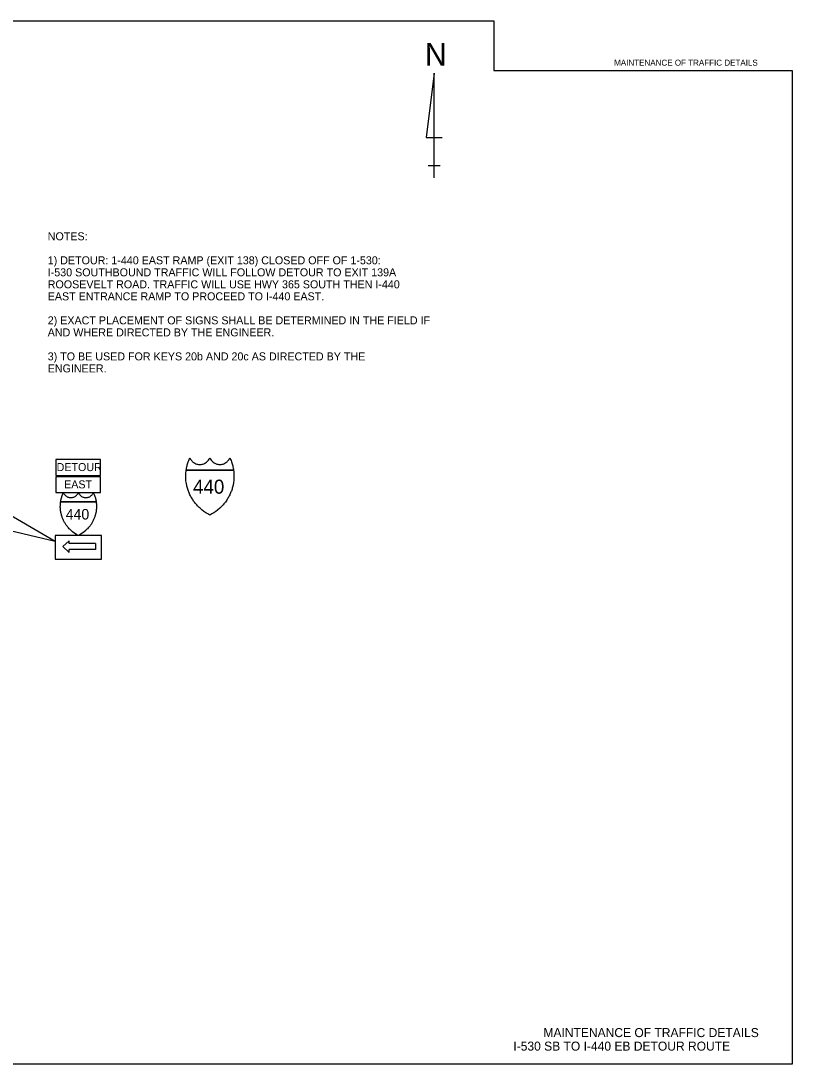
# Model space of a CAD drawing. Extents: x 754662 to 914198, y 935180 to 1039412.
# Drawn here: x 837096 to 914198, y 935180 to 1039412 of the extents above; entities that cross this region are included whole.
import ezdxf

# ---------------------------------------------------------------- set-up
doc = ezdxf.new("R2010")
doc.units = 0
for name, color, linetype in [('G-ANNO-TEXT', 7, 'Continuous'), ('G-No Plot-Anchor', 7, 'Continuous'), ('Level 14', 7, 'Continuous'), ('Level 61', 7, 'Continuous'), ('Level 62', 7, 'Continuous'), ('R_Draft', 7, 'Continuous')]:
    doc.layers.add(name, color=color, linetype=linetype)

msp = doc.modelspace()

# ---------------------------------------------------------------- linework, layer by layer
at = {"layer": 'G-No Plot-Anchor'}
msp.add_lwpolyline([(870863, 1039412), (884363, 1039412), (884363, 1034457), (914198, 1034457), (914198, 935180), (754662, 935180), (754662, 1039412)], close=True, dxfattribs=at)
at = {"layer": 'Level 14'}
for points in [[(853626, 994520), (853643, 994633), (853661, 994733), (853687, 994862), (853707, 994946), (853732, 995045), (853765, 995163), (853795, 995261), (853829, 995362), (853874, 995486), (853921, 995602), (853959, 995693), (853991, 995764), (854026, 995687), (854066, 995614), (854111, 995547), (854168, 995472), (854214, 995422), (854270, 995367), (854327, 995320), (854389, 995275), (854487, 995216), (854587, 995169), (854679, 995137), (854769, 995114), (854865, 995098), (854978, 995090), (855051, 995092), (855136, 995100), (855212, 995113), (855292, 995132), (855374, 995159), (855483, 995208), (855559, 995250), (855646, 995310), (855731, 995381), (855792, 995443), (855862, 995528), (855920, 995614), (855954, 995675), (855991, 995755)], [(855991, 995755), (856028, 995675), (856062, 995614), (856120, 995528), (856190, 995443), (856252, 995381), (856336, 995310), (856423, 995250), (856499, 995208), (856608, 995159), (856690, 995132), (856771, 995113), (856846, 995100), (856931, 995092), (857005, 995090), (857117, 995098), (857214, 995114), (857304, 995137), (857395, 995169), (857495, 995216), (857594, 995275), (857655, 995320), (857712, 995367), (857769, 995422), (857814, 995472), (857872, 995547), (857916, 995614), (857956, 995687), (857991, 995764), (858023, 995693), (858062, 995602), (858108, 995486), (858153, 995362), (858187, 995261), (858217, 995163), (858250, 995045), (858275, 994946), (858295, 994862), (858321, 994733), (858339, 994633), (858357, 994520)], [(855991, 990038), (855784, 990149), (855601, 990259), (855401, 990394), (855214, 990536), (855009, 990710), (854932, 990781), (854846, 990867), (854765, 990950), (854677, 991046), (854590, 991147), (854518, 991236), (854440, 991338), (854369, 991436), (854307, 991527), (854253, 991610), (854208, 991682), (854149, 991783), (854103, 991866), (854052, 991963), (854003, 992063), (853960, 992155), (853921, 992245), (853881, 992345), (853845, 992438), (853811, 992535), (853778, 992636), (853747, 992739), (853720, 992838), (853696, 992932), (853677, 993016), (853664, 993078), (853642, 993199), (853620, 993338), (853605, 993454), (853595, 993576), (853588, 993675), (853584, 993800), (853583, 993917), (853585, 994047), (853589, 994133), (853593, 994211), (853597, 994261), (853609, 994389), (853626, 994520)], [(858357, 994520), (853626, 994520)], [(853626, 994520), (858357, 994520)], [(858357, 994520), (858373, 994389), (858385, 994261), (858389, 994211), (858394, 994133), (858397, 994047), (858400, 993917), (858398, 993800), (858394, 993675), (858388, 993576), (858377, 993454), (858362, 993338), (858341, 993199), (858318, 993078), (858305, 993016), (858286, 992932), (858263, 992838), (858235, 992739), (858204, 992636), (858171, 992535), (858137, 992438), (858102, 992345), (858061, 992245), (858022, 992155), (857979, 992063), (857930, 991963), (857879, 991866), (857833, 991783), (857774, 991682), (857729, 991610), (857675, 991527), (857613, 991436), (857542, 991338), (857464, 991236), (857392, 991147), (857305, 991046), (857217, 990950), (857137, 990867), (857050, 990781), (856973, 990710), (856769, 990536), (856581, 990394), (856381, 990259), (856198, 990149), (855991, 990038)], [(842848, 987991), (842692, 988074), (842556, 988156), (842405, 988258), (842265, 988364), (842111, 988495), (842054, 988549), (841989, 988612), (841928, 988675), (841862, 988747), (841797, 988823), (841743, 988889), (841684, 988966), (841631, 989040), (841585, 989107), (841544, 989170), (841511, 989224), (841466, 989300), (841432, 989362), (841394, 989434), (841357, 989509), (841325, 989579), (841296, 989646), (841265, 989721), (841238, 989791), (841213, 989863), (841188, 989939), (841165, 990017), (841144, 990091), (841127, 990162), (841112, 990225), (841103, 990271), (841086, 990362), (841069, 990466), (841058, 990553), (841050, 990644), (841046, 990719), (841042, 990813), (841041, 990900), (841043, 990998), (841046, 991062), (841049, 991121), (841052, 991158), (841061, 991254), (841074, 991352)], [(841074, 991352), (841087, 991437), (841100, 991512), (841120, 991609), (841134, 991672), (841153, 991747), (841178, 991835), (841201, 991908), (841226, 991984), (841260, 992077), (841295, 992164), (841324, 992232), (841348, 992285), (841374, 992228), (841404, 992173), (841437, 992122), (841481, 992067), (841515, 992029), (841557, 991988), (841600, 991952), (841646, 991919), (841719, 991874), (841795, 991839), (841863, 991815), (841931, 991798), (842003, 991786), (842088, 991780), (842143, 991781), (842207, 991787), (842263, 991797), (842324, 991812), (842385, 991832), (842467, 991868), (842523, 991900), (842589, 991945), (842652, 991998), (842698, 992044), (842751, 992108), (842794, 992173), (842820, 992219), (842848, 992279)], [(844622, 991352), (841074, 991352)], [(841074, 991352), (844622, 991352)], [(842848, 992279), (842876, 992219), (842901, 992173), (842945, 992108), (842997, 992044), (843043, 991998), (843106, 991945), (843172, 991900), (843229, 991868), (843311, 991832), (843372, 991812), (843432, 991797), (843489, 991787), (843553, 991781), (843608, 991780), (843692, 991786), (843765, 991798), (843832, 991815), (843900, 991839), (843976, 991874), (844050, 991919), (844096, 991952), (844139, 991988), (844181, 992029), (844215, 992067), (844258, 992122), (844291, 992173), (844321, 992228), (844348, 992285), (844372, 992232), (844401, 992164), (844435, 992077), (844469, 991984), (844495, 991908), (844517, 991835), (844542, 991747), (844561, 991672), (844576, 991609), (844596, 991512), (844609, 991437), (844622, 991352)], [(844622, 991352), (844634, 991254), (844643, 991158), (844646, 991121), (844650, 991062), (844652, 990998), (844654, 990900), (844653, 990813), (844650, 990719), (844645, 990644), (844637, 990553), (844626, 990466), (844610, 990362), (844593, 990271), (844583, 990225), (844569, 990162), (844551, 990091), (844531, 990017), (844508, 989939), (844483, 989863), (844457, 989791), (844431, 989721), (844400, 989646), (844371, 989579), (844339, 989509), (844302, 989434), (844264, 989362), (844229, 989300), (844185, 989224), (844151, 989170), (844111, 989107), (844065, 989040), (844011, 988966), (843953, 988889), (843898, 988823), (843833, 988747), (843767, 988675), (843707, 988612), (843642, 988549), (843584, 988495), (843431, 988364), (843290, 988258), (843140, 988156), (843003, 988074), (842848, 987991)]]:
    msp.add_lwpolyline(points, dxfattribs=at)
at = {"layer": 'Level 61'}
msp.add_line((844567, 987181), (844567, 986595), dxfattribs=at)
at = {"layer": 'Level 62'}
for p, q in [((841292, 986888), (841935, 987474)), ((841935, 987181), (841935, 987474)), ((844567, 987181), (841935, 987181)), ((841935, 986302), (841292, 986888)), ((844567, 986595), (841935, 986595)), ((841935, 986302), (841935, 986595))]:
    msp.add_line(p, q, dxfattribs=at)
for points in [[(840604, 994006), (845060, 994006), (845060, 995579), (840604, 995579)], [(840604, 992279), (845060, 992279), (845060, 993852), (840604, 993852)], [(840540, 985630), (845156, 985630), (845156, 987991), (840540, 987991)]]:
    msp.add_lwpolyline(points, close=True, dxfattribs=at)
at = {"layer": 'R_Draft'}
for p, q in [((878417, 1034171), (877615, 1027755)), ((878417, 1023745), (878417, 1034171)), ((877615, 1027755), (879219, 1027755)), ((877811, 1024963), (879014, 1024963)), ((840540, 987412), (813952, 1002723)), ((840540, 987412), (828507, 990224))]:
    msp.add_line(p, q, dxfattribs=at)

# ---------------------------------------------------------------- texts
at = {"layer": 'G-ANNO-TEXT'}
for s, height, p in [('MAINTENANCE OF TRAFFIC DETAILS', 600, (896406, 1034935)), ('440', 1402.1, (854306, 992171)), ('440', 1051.6, (841584, 989591)), ('MAINTENANCE OF TRAFFIC DETAILS', 900, (889335, 937880)), ('I-530 SB TO I-440 EB DETOUR ROUTE', 900, (886330, 936530))]:
    msp.add_text(s, height=height, dxfattribs=at).set_placement(p)
at = {"layer": 'R_Draft'}
for s, height, p in [('N', 2250, (877490, 1034952)), ('NOTES:', 800, (839783, 1017489)), ('1) DETOUR: 1-440 EAST RAMP (EXIT 138) CLOSED OFF OF 1-530:', 800, (839783, 1015089)), ('I-530 SOUTHBOUND TRAFFIC WILL FOLLOW DETOUR TO EXIT 139A', 800, (839783, 1013889)), ('ROOSEVELT ROAD. TRAFFIC WILL USE HWY 365 SOUTH THEN I-440', 800, (839783, 1012689)), ('EAST ENTRANCE RAMP TO PROCEED TO I-440 EAST.', 800, (839783, 1011489)), ('2) EXACT PLACEMENT OF SIGNS SHALL BE DETERMINED IN THE FIELD IF ', 800, (839783, 1009089)), ('AND WHERE DIRECTED BY THE ENGINEER.', 800, (839783, 1007889)), ('3) TO BE USED FOR KEYS 20b AND 20c AS DIRECTED BY THE', 800, (839783, 1005489)), ('ENGINEER.', 800, (839783, 1004289)), ('DETOUR', 800, (840672, 994430)), ('EAST', 800, (841421, 992703))]:
    msp.add_text(s, height=height, dxfattribs=at).set_placement(p)

doc.saveas('drawing.dxf')
